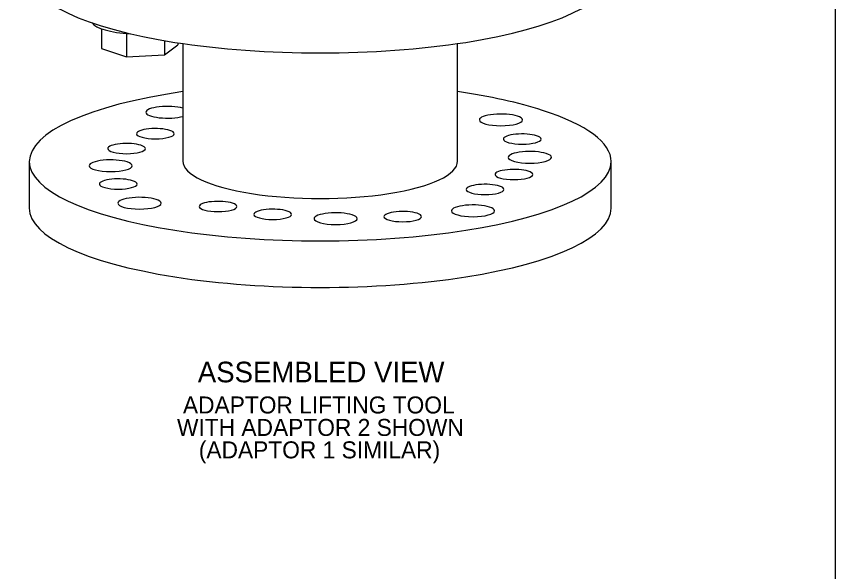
# Model space of a CAD drawing. Extents: x 99862 to 103151, y 100000 to 114076.
# Drawn here: x 102356 to 103151, y 113038 to 113577 of the extents above; entities that cross this region are included whole.
import ezdxf

# ---------------------------------------------------------------- set-up
doc = ezdxf.new("R2010")
doc.units = 0
for name, color, linetype in [('Default', 7, 'Continuous'), ('Level 1', 7, 'Continuous'), ('Level 20', 7, 'Continuous')]:
    doc.layers.add(name, color=color, linetype=linetype)

msp = doc.modelspace()

# ---------------------------------------------------------------- linework, layer by layer
at = {"layer": 'Default'}
for p, q in [((102438.66, 113564.46), (102438.66, 113545.21)), ((102462.96, 113559.92), (102462.96, 113537.37)), ((102499.99, 113552.97), (102499.99, 113539.19)), ((102512.73, 113550.9), (102512.73, 113548.85)), ((102517.73, 113550.15), (102517.73, 113436.06)), ((102784.29, 113436.06), (102784.29, 113550.15)), ((102438.66, 113545.21), (102462.96, 113537.37)), ((102499.99, 113539.19), (102512.73, 113548.85)), ((102462.96, 113537.37), (102499.99, 113539.19)), ((102368.77, 113435.62), (102368.77, 113390.36)), ((102933.25, 113390.36), (102933.25, 113435.62))]:
    msp.add_line(p, q, dxfattribs=at)
for centre, major_axis, start_param, end_param in [((102475.7, 113572.1), (-46.41, 0), 0.150131, 1.380216), ((102651.01, 113435.62), (-282.24, 0), 5.204199, 6.283185), ((102651.01, 113435.62), (-282.24, 0), 3.843377, 4.220579), ((102502.81, 113483.45), (20.95, 0), 0.778364, 3.141593), ((102502.81, 113483.45), (20.95, 0), 3.141593, 5.504822), ((102826.32, 113476.05), (20.95, 0), 0.701785, 3.141593), ((102826.32, 113476.05), (20.95, 0), 6.283185, 6.98497), ((102651.01, 113435.62), (-282.24, 0), 3.141593, 3.843377), ((102826.32, 113476.05), (20.95, 0), 3.141593, 6.283185), ((102491.08, 113462.66), (18.29, 0), 0.701785, 3.141593), ((102491.08, 113462.66), (18.29, 0), 3.141593, 6.283185), ((102491.08, 113462.66), (18.29, 0), 6.283185, 6.98497), ((102846.99, 113457.45), (18.29, 0), 0.701785, 3.141593), ((102846.99, 113457.45), (18.29, 0), 3.141593, 6.283185), ((102846.99, 113457.45), (18.29, 0), 6.283185, 6.98497), ((102463.15, 113448.2), (18.29, 0), 0.701785, 3.141593), ((102463.15, 113448.2), (18.29, 0), 3.141593, 6.283185), ((102463.15, 113448.2), (18.29, 0), 6.283185, 6.98497), ((102854.3, 113439.7), (20.95, 0), 0.701785, 3.141593), ((102854.3, 113439.7), (20.95, 0), 3.141593, 6.283185), ((102854.3, 113439.7), (20.95, 0), 6.283185, 6.98497), ((102651.01, 113435.62), (-282.24, 0), 6.283185, 9.424778), ((102447.72, 113431.53), (20.95, 0), 0.701785, 3.141593), ((102447.72, 113431.53), (20.95, 0), 3.141593, 6.283185), ((102447.72, 113431.53), (20.95, 0), 6.283185, 6.98497), ((102651.01, 113436.06), (-133.28, 0), 6.283185, 9.424778), ((102838.86, 113423.04), (18.29, 0), 0.701785, 3.141593), ((102838.86, 113423.04), (18.29, 0), 3.141593, 6.283185), ((102838.86, 113423.04), (18.29, 0), 6.283185, 6.98497), ((102455.03, 113413.79), (18.29, 0), 0.701785, 3.141593), ((102455.03, 113413.79), (18.29, 0), 6.283185, 6.98497), ((102455.03, 113413.79), (18.29, 0), 3.141593, 6.283185), ((102810.94, 113408.57), (18.29, 0), 0.701785, 3.141593), ((102810.94, 113408.57), (18.29, 0), 3.141593, 6.283185), ((102810.94, 113408.57), (18.29, 0), 6.283185, 6.98497), ((102475.7, 113395.18), (20.95, 0), 0.701785, 3.141593), ((102475.7, 113395.18), (20.95, 0), 6.283185, 6.98497), ((102475.7, 113395.18), (20.95, 0), 3.141593, 6.283185), ((102551.88, 113391.98), (18.29, 0), 0.701785, 3.141593), ((102551.88, 113391.98), (18.29, 0), 3.141593, 6.283185), ((102551.88, 113391.98), (18.29, 0), 6.283185, 6.98497), ((102799.21, 113387.78), (20.95, 0), 0.701785, 3.141593), ((102799.21, 113387.78), (20.95, 0), 6.283185, 6.98497), ((102651.01, 113390.36), (-282.24, 0), 6.283185, 9.424778), ((102604.9, 113384.36), (18.29, 0), 0.701785, 3.141593), ((102604.9, 113384.36), (18.29, 0), 3.141593, 6.283185), ((102604.9, 113384.36), (18.29, 0), 6.283185, 6.98497), ((102665.97, 113380.15), (20.95, 0), 0.701785, 3.141593), ((102665.97, 113380.15), (20.95, 0), 6.283185, 6.98497), ((102731.02, 113382.15), (18.29, 0), 0.701785, 3.141593), ((102731.02, 113382.15), (18.29, 0), 6.283185, 6.98497), ((102799.21, 113387.78), (20.95, 0), 3.141593, 6.283185), ((102665.97, 113380.15), (20.95, 0), 3.141593, 6.283185), ((102731.02, 113382.15), (18.29, 0), 3.141593, 6.283185)]:
    msp.add_ellipse(centre, major_axis=major_axis, ratio=0.272841, start_param=start_param, end_param=end_param, dxfattribs=at)
at = {"layer": 'Level 1'}
msp.add_lwpolyline([(99862, 111999.5), (103151, 111999.5), (103151, 114075.5), (99862, 114075.5)], close=True, dxfattribs=at)
at = {"layer": 'Level 20'}
msp.add_ellipse((102651.01, 113618.03), major_axis=(-282.24, 0), ratio=0.272841, start_param=6.283185, end_param=9.424778, dxfattribs=at)

# ---------------------------------------------------------------- texts
for s, height, p in [('ASSEMBLED VIEW', 20, (102532.24, 113221.29)), ('ADAPTOR LIFTING TOOL ', 16.5, (102517.8, 113191.04)), ('WITH ADAPTOR 2 SHOWN', 16.5, (102512.04, 113169.25)), ('(ADAPTOR 1 SIMILAR)', 16.5, (102533.2, 113147.46))]:
    msp.add_text(s, height=height, dxfattribs=at).set_placement(p)

doc.saveas('drawing.dxf')
